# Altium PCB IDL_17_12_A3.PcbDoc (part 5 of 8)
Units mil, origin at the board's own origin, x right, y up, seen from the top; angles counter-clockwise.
Board outline 5119.97 x 10350 mil, 6 copper layers (Top Signal, 3.3 Volt, GND, 5 Volt, Split Plane, Bot Signal), stack 66.2 mil thick; 510 components, 178 nets, 2317 pads, 385 vias.
Unrouted connection lines stored in the file: 1.
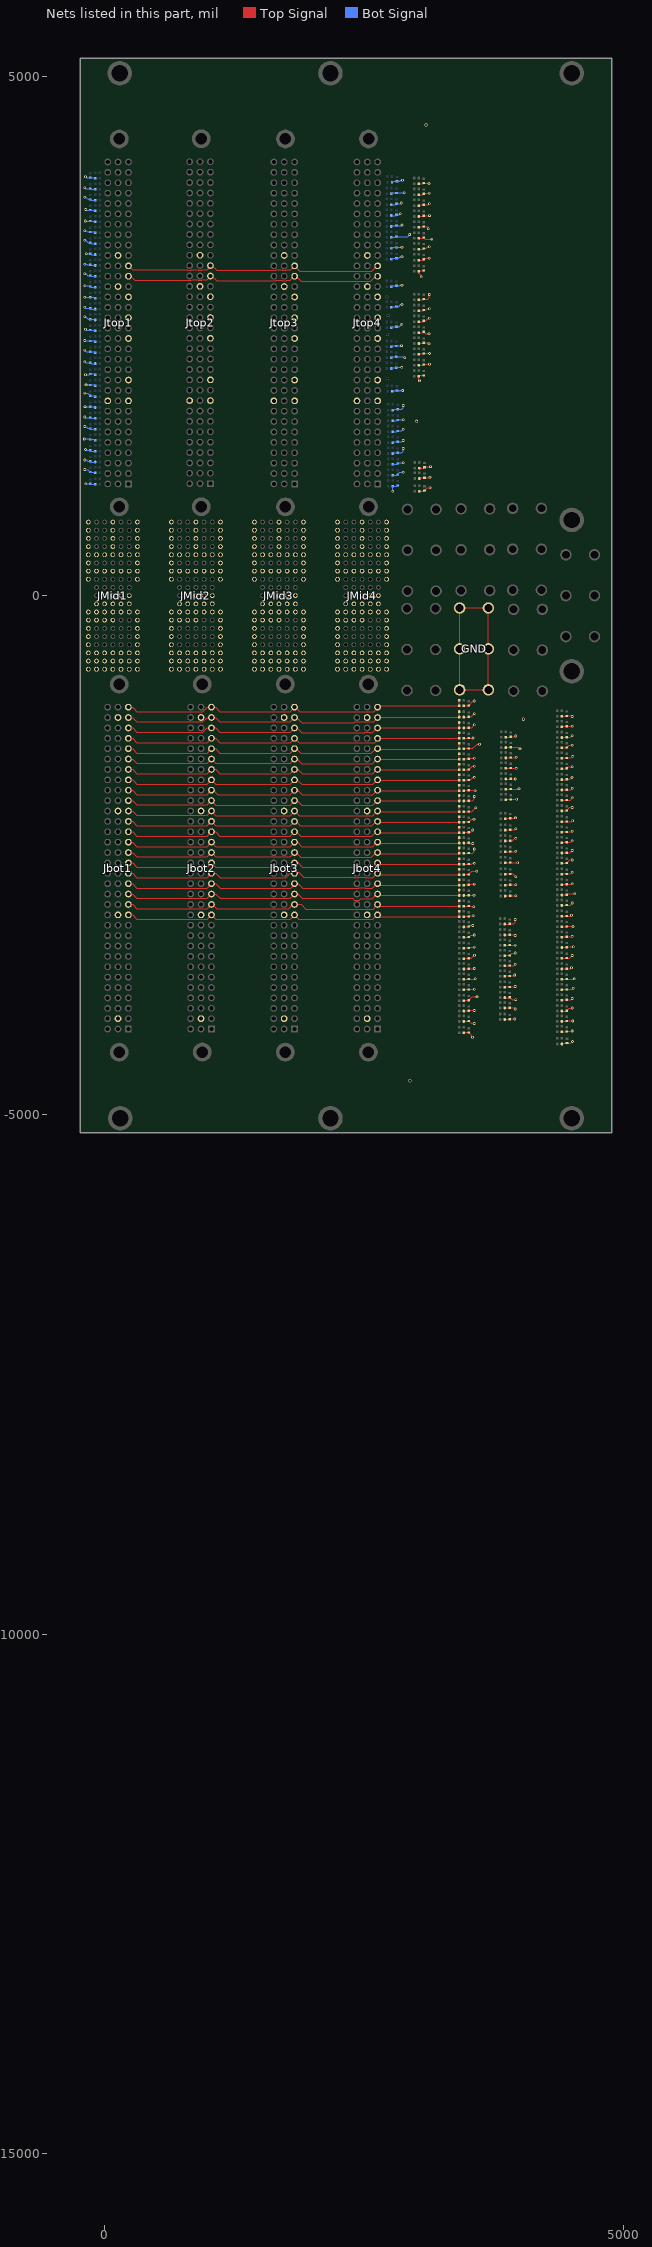
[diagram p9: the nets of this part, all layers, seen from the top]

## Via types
v1: diameter 25.59, hole 11.81, Top Signal to Bot Signal, 385 vias

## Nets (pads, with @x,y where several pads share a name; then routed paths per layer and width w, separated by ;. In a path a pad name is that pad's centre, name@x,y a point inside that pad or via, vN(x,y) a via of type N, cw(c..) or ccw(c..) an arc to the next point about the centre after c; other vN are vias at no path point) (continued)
GND: CR_IDL_17_12_TerA1.1 CR_IDL_17_12_TerA2.1 CR_IDL_17_12_TerA3.1 CR_IDL_17_12_TerA4.1 CR_IDL_17_12_TerA5.1 CR_IDL_17_12_TerA6.1 CR_IDL_17_12_TerA7.1 CR_IDL_17_12_TerA8.1 CR_IDL_17_12_TerA9.1 CR_IDL_17_12_TerA10.1 CR_IDL_17_12_TerA11.1 CR_IDL_17_12_TerA12.1 CR_IDL_17_12_TerA13.1 CR_IDL_17_12_TerA14.1 CR_IDL_17_12_TerA15.1 CR_IDL_17_12_TerA16.1 CR_IDL_17_12_TerA17.1 CR_IDL_17_12_TerA18.1 CR_IDL_17_12_TerA19.1 CR_IDL_17_12_TerA20.1 CR_IDL_17_12_TerA21.1 CR_IDL_17_12_TerA22.1 CR_IDL_17_12_TerA23.1 CR_IDL_17_12_TerA24.1 CR_IDL_17_12_TerA25.1 CR_IDL_17_12_TerA26.1 CR_IDL_17_12_TerA27.1 CR_IDL_17_12_TerA28.1 CR_IDL_17_12_TerA29.1 CR_IDL_17_12_TerA30.1 CR_IDL_17_12_TerA31.1 CR_IDL_17_12_TerA32.1 CR_IDL_17_12_TerA33.1 CR_IDL_17_12_TerA34.1 CR_IDL_17_12_TerA35.1 CR_IDL_17_12_TerA36.1 CR_IDL_17_12_TerA37.1 CR_IDL_17_12_TerA38.1 CR_IDL_17_12_TerA39.1 CR_IDL_17_12_TerA40.1 CR_IDL_17_12_TerA41.1 CR_IDL_17_12_TerA42.1 CR_IDL_17_12_TerA43.1 CR_IDL_17_12_TerA44.1 CR_IDL_17_12_TerA45.1 CR_IDL_17_12_TerA46.1 CR_IDL_17_12_TerA47.1 CR_IDL_17_12_TerA48.1 CR_IDL_17_12_TerA49.1 CR_IDL_17_12_TerA50.1 CR_IDL_17_12_TerA51.1 CR_IDL_17_12_TerA52.1 CR_IDL_17_12_TerA53.1 CR_IDL_17_12_TerA54.1 CR_IDL_17_12_TerA55.1 CR_IDL_17_12_TerA56.1 CR_IDL_17_12_TerA57.1 CR_IDL_17_12_TerA58.1 CR_IDL_17_12_TerA59.1 CR_IDL_17_12_TerA60.1 CR_IDL_17_12_TerA61.1 CR_IDL_17_12_TerA62.1 CR_IDL_17_12_TerA63.1 CR_IDL_17_12_TerA64.1 CR_IDL_17_12_TerA65.1 CR_IDL_17_12_TerA66.1 CR_IDL_17_12_TerA67.1 CR_IDL_17_12_TerA68.1 CR_IDL_17_12_TerA69.1 CR_IDL_17_12_TerA70.1 CR_IDL_17_12_TerA71.1 CR_IDL_17_12_TerA72.1 CRB_IDL_17_12_TerB1.1 CRB_IDL_17_12_TerB2.1 CRB_IDL_17_12_TerB3.1 CRB_IDL_17_12_TerB4.1 CRB_IDL_17_12_TerB5.1 CRB_IDL_17_12_TerB6.1 CRB_IDL_17_12_TerB7.1 CRB_IDL_17_12_TerB8.1 CRB_IDL_17_12_TerB9.1 CRB_IDL_17_12_TerB10.1 CRB_IDL_17_12_TerB11.1 CRB_IDL_17_12_TerB12.1 CRB_IDL_17_12_TerB13.1 CRB_IDL_17_12_TerB14.1 CRB_IDL_17_12_TerB15.1 CRB_IDL_17_12_TerB16.1 CRB_IDL_17_12_TerB17.1 CRB_IDL_17_12_TerB18.1 CRB_IDL_17_12_TerB19.1 CRB_IDL_17_12_TerB20.1 CRB_IDL_17_12_TerB21.1 CRB_IDL_17_12_TerB22.1 CRB_IDL_17_12_TerB23.1 CRB_IDL_17_12_TerB24.1 CRB_IDL_17_12_TerB25.1 CRB_IDL_17_12_TerB26.1 CRB_IDL_17_12_TerB27.1 CRB_IDL_17_12_TerB28.1 CRB_IDL_17_12_TerB29.1 CRB_IDL_17_12_TerB30.1 CRB_IDL_17_12_TerB31.1 CRB_IDL_17_12_TerB32.1 CRB_IDL_17_12_TerB33.1 CRB_IDL_17_12_TerB34.1 CRB_IDL_17_12_TerB35.1 CRB_IDL_17_12_TerB36.1 CRB_IDL_17_12_TerB37.1 CRB_IDL_17_12_TerB38.1 CRB_IDL_17_12_TerB39.1 CRB_IDL_17_12_TerB40.1 CRB_IDL_17_12_TerB41.1 CRB_IDL_17_12_TerB42.1 CRB_IDL_17_12_TerB43.1 CRB_IDL_17_12_TerB44.1 CRB_IDL_17_12_TerB45.1 CRB_IDL_17_12_TerB46.1 CRB_IDL_17_12_TerB47.1 CRB_IDL_17_12_TerB48.1 CRB_IDL_17_12_TerB49.1 CRB_IDL_17_12_TerB50.1 CRB_IDL_17_12_TerB51.1 CRB_IDL_17_12_TerB52.1 CRB_IDL_17_12_TerB53.1 CRB_IDL_17_12_TerB54.1 CRB_IDL_17_12_TerB55.1 CRB_IDL_17_12_TerB56.1 CRB_IDL_17_12_TerB57.1 CRB_IDL_17_12_TerB58.1 CRB_IDL_17_12_TerB59.1 CRB_IDL_17_12_TerB60.1 CRB_IDL_17_12_TerB61.1 CRB_IDL_17_12_TerB62.1 CRB_IDL_17_12_TerB63.1 CRB_IDL_17_12_TerB64.1 CRB_IDL_17_12_TerB65.1 CRB_IDL_17_12_TerB66.1 CRB_IDL_17_12_TerB67.1 CRB_IDL_17_12_TerB68.1 CRB_IDL_17_12_TerB69.1 CRB_IDL_17_12_TerB70.1 CRB_IDL_17_12_TerB71.1 CRB_IDL_17_12_TerB72.1 CRB_IDL_17_12_TerB73.1 CRB_IDL_17_12_TerB74.1 CRB_IDL_17_12_TerB75.1 CRB_IDL_17_12_TerB76.1 CRB_IDL_17_12_TerB77.1 CRB_IDL_17_12_TerB78.1 CRB_IDL_17_12_TerB79.1 CRB_IDL_17_12_TerB80.1 CRB_IDL_17_12_TerB81.1 CRB_IDL_17_12_TerB82.1 CRB_IDL_17_12_TerB83.1 CRB_IDL_17_12_TerB84.1 CRB_IDL_17_12_TerB85.1 CRB_IDL_17_12_TerB86.1 CRB_IDL_17_12_TerB87.1 CRB_IDL_17_12_TerB88.1 CRB_IDL_17_12_TerB89.1 GND.1 GND.2 GND.3 GND.4 GND.5 GND.6 Jbot1.B2 Jbot1.B12 Jbot1.B22 Jbot1.B31 Jbot2.B2 Jbot2.B12 Jbot2.B22 Jbot2.B31 Jbot3.B2 Jbot3.B12 Jbot3.B22 Jbot3.B31 Jbot4.B2 Jbot4.B12 Jbot4.B22 Jbot4.B31 JMid1.1 JMid1.2 JMid1.3 JMid1.4 JMid1.5 JMid1.6 JMid1.7 JMid1.8 JMid1.9 JMid1.10 JMid1.11 JMid1.12 JMid1.13 JMid1.14 JMid1.15 JMid1.16 JMid1.17 JMid1.18 JMid1.19 JMid1.24 JMid1.25 JMid1.26 JMid1.29 JMid1.31 JMid1.36 JMid1.37 JMid1.38 JMid1.43 JMid1.44 JMid1.45 JMid1.48 JMid1.50 JMid1.55 JMid1.56 JMid1.57 JMid1.61 JMid1.62 JMid1.63 JMid1.64 JMid1.67 JMid1.69 JMid1.70 JMid1.71 JMid1.72 JMid1.73 JMid1.74 JMid1.75 JMid1.76 JMid1.80 JMid1.81 JMid1.82 JMid1.86 JMid1.88 JMid1.93 JMid1.94 JMid1.95 JMid1.99 JMid1.100 JMid1.101 JMid1.105 JMid1.107 JMid1.112 JMid1.113 JMid1.114 JMid1.115 JMid1.116 JMid1.117 JMid1.118 JMid1.119 JMid1.120 JMid1.121 JMid1.122 JMid1.123 JMid1.124 JMid1.125 JMid1.126 JMid1.127 JMid2.1 JMid2.2 JMid2.3 JMid2.4 JMid2.5 JMid2.6 JMid2.7 JMid2.8 JMid2.9 JMid2.10 JMid2.11 JMid2.12 JMid2.13 JMid2.14 JMid2.15 JMid2.16 JMid2.17 JMid2.18 JMid2.19 JMid2.24 JMid2.25 JMid2.26 JMid2.29 JMid2.31 JMid2.36 JMid2.37 JMid2.38 JMid2.43 JMid2.44 JMid2.45 JMid2.48 JMid2.50 JMid2.55 JMid2.56 JMid2.57 JMid2.61 JMid2.62 JMid2.63 JMid2.64 JMid2.67 JMid2.69 JMid2.70 JMid2.71 JMid2.72 JMid2.73 JMid2.74 JMid2.75 JMid2.76 JMid2.80 JMid2.81 JMid2.82 JMid2.86 JMid2.88 JMid2.93 JMid2.94 JMid2.95 JMid2.99 JMid2.100 JMid2.101 JMid2.105 JMid2.107 JMid2.112 JMid2.113 JMid2.114 JMid2.115 JMid2.116 JMid2.117 JMid2.118 JMid2.119 JMid2.120 JMid2.121 JMid2.122 JMid2.123 JMid2.124 JMid2.125 JMid2.126 JMid2.127 JMid3.1 JMid3.2 JMid3.3 JMid3.4 JMid3.5 JMid3.6 JMid3.7 JMid3.8 JMid3.9 JMid3.10 JMid3.11 JMid3.12 JMid3.13 JMid3.14 JMid3.15 JMid3.16 JMid3.17 JMid3.18 JMid3.19 JMid3.24 JMid3.25 JMid3.26 JMid3.29 JMid3.31 JMid3.36 JMid3.37 JMid3.38 JMid3.43 JMid3.44 JMid3.45 JMid3.48 JMid3.50 JMid3.55 JMid3.56 JMid3.57 JMid3.61 JMid3.62 JMid3.63 JMid3.64 JMid3.67 JMid3.69 JMid3.70 JMid3.71 JMid3.72 JMid3.73 JMid3.74 JMid3.75 JMid3.76 JMid3.80 JMid3.81 JMid3.82 JMid3.86 JMid3.88 JMid3.93 JMid3.94 JMid3.95 JMid3.99 JMid3.100 JMid3.101 JMid3.105 JMid3.107 JMid3.112 JMid3.113 JMid3.114 JMid3.115 JMid3.116 JMid3.117 JMid3.118 JMid3.119 JMid3.120 JMid3.121 JMid3.122 JMid3.123 JMid3.124 JMid3.125 JMid3.126 JMid3.127 JMid4.1 JMid4.2 JMid4.3 JMid4.4 JMid4.5 JMid4.6 JMid4.7 JMid4.8 JMid4.9 JMid4.10 JMid4.11 JMid4.12 JMid4.13 JMid4.14 JMid4.15 JMid4.16 JMid4.17 JMid4.18 JMid4.19 JMid4.24 JMid4.25 JMid4.26 JMid4.29 JMid4.31 JMid4.36 JMid4.37 JMid4.38 JMid4.43 JMid4.44 JMid4.45 JMid4.48 JMid4.50 JMid4.55 JMid4.56 JMid4.57 JMid4.61 JMid4.62 JMid4.63 JMid4.64 JMid4.67 JMid4.69 JMid4.70 JMid4.71 JMid4.72 JMid4.73 JMid4.74 JMid4.75 JMid4.76 JMid4.80 JMid4.81 JMid4.82 JMid4.86 JMid4.88 JMid4.93 JMid4.94 JMid4.95 JMid4.99 JMid4.100 JMid4.101 JMid4.105 JMid4.107 JMid4.112 JMid4.113 JMid4.114 JMid4.115 JMid4.116 JMid4.117 JMid4.118 JMid4.119 JMid4.120 JMid4.121 JMid4.122 JMid4.123 JMid4.124 JMid4.125 JMid4.126 JMid4.127 Jtop1.A9 Jtop1.A11 Jtop1.A15 Jtop1.A17 Jtop1.A19 Jtop1.B20 Jtop1.B23 Jtop1.C9 Jtop2.A9 Jtop2.A11 Jtop2.A15 Jtop2.A17 Jtop2.A19 Jtop2.B20 Jtop2.B23 Jtop2.C9 Jtop3.A9 Jtop3.A11 Jtop3.A15 Jtop3.A17 Jtop3.A19 Jtop3.B20 Jtop3.B23 Jtop3.C9 Jtop4.A9 Jtop4.A11 Jtop4.A15 Jtop4.A17 Jtop4.A19 Jtop4.B20 Jtop4.B23 Jtop4.C9 R2R_IDL_17_12_TerA1.1 R2R_IDL_17_12_TerA2.1 R2R_IDL_17_12_TerA3.1 R2R_IDL_17_12_TerA4.1 R2R_IDL_17_12_TerA5.1 R2R_IDL_17_12_TerA6.1 R2R_IDL_17_12_TerA7.1 R2R_IDL_17_12_TerA8.1 R2R_IDL_17_12_TerA9.1 R2R_IDL_17_12_TerA10.1 R2R_IDL_17_12_TerA11.1 R2R_IDL_17_12_TerA12.1 R2R_IDL_17_12_TerA13.1 R2R_IDL_17_12_TerA14.1 R2R_IDL_17_12_TerA15.1 R2R_IDL_17_12_TerA16.1 R2R_IDL_17_12_TerA17.1 R2R_IDL_17_12_TerA18.1 R2R_IDL_17_12_TerA19.1 R2R_IDL_17_12_TerA20.1 R2R_IDL_17_12_TerA21.1 R2R_IDL_17_12_TerA22.1 R2R_IDL_17_12_TerA23.1 R2R_IDL_17_12_TerA24.1 R2R_IDL_17_12_TerA25.1 R2R_IDL_17_12_TerA26.1 R2R_IDL_17_12_TerA27.1 R2R_IDL_17_12_TerA28.1 R2R_IDL_17_12_TerA29.1 R2R_IDL_17_12_TerA30.1 R2R_IDL_17_12_TerA31.1 R2R_IDL_17_12_TerA32.1 R2R_IDL_17_12_TerA33.1 R2R_IDL_17_12_TerA34.1 R2R_IDL_17_12_TerA35.1 R2R_IDL_17_12_TerA36.1 R2R_IDL_17_12_TerA37.1 R2R_IDL_17_12_TerA38.1 R2R_IDL_17_12_TerA39.1 R2R_IDL_17_12_TerA40.1 R2R_IDL_17_12_TerA41.1 R2R_IDL_17_12_TerA42.1 R2R_IDL_17_12_TerA43.1 R2R_IDL_17_12_TerA44.1 R2R_IDL_17_12_TerA45.1 R2R_IDL_17_12_TerA46.1 R2R_IDL_17_12_TerA47.1 R2R_IDL_17_12_TerA48.1 R2R_IDL_17_12_TerA49.1 R2R_IDL_17_12_TerA50.1 R2R_IDL_17_12_TerA51.1 R2R_IDL_17_12_TerA52.1 R2R_IDL_17_12_TerA53.1 R2R_IDL_17_12_TerA54.1 R2R_IDL_17_12_TerA55.1 R2R_IDL_17_12_TerA56.1 R2R_IDL_17_12_TerA57.1 R2R_IDL_17_12_TerA58.1 R2R_IDL_17_12_TerA59.1 R2R_IDL_17_12_TerA60.1 R2R_IDL_17_12_TerA61.1 R2R_IDL_17_12_TerA62.1 R2R_IDL_17_12_TerA63.1 R2R_IDL_17_12_TerA64.1 R2R_IDL_17_12_TerA65.1 R2R_IDL_17_12_TerA66.1 R2R_IDL_17_12_TerA67.1 R2R_IDL_17_12_TerA68.1 R2R_IDL_17_12_TerA69.1 R2R_IDL_17_12_TerA70.1 R2R_IDL_17_12_TerA71.1 R2R_IDL_17_12_TerA72.1 R2RB_IDL_17_12_TerB1.1 R2RB_IDL_17_12_TerB2.1 R2RB_IDL_17_12_TerB3.1 R2RB_IDL_17_12_TerB4.1 R2RB_IDL_17_12_TerB5.1 R2RB_IDL_17_12_TerB6.1 R2RB_IDL_17_12_TerB7.1 R2RB_IDL_17_12_TerB8.1 R2RB_IDL_17_12_TerB9.1 R2RB_IDL_17_12_TerB10.1 R2RB_IDL_17_12_TerB11.1 R2RB_IDL_17_12_TerB12.1 R2RB_IDL_17_12_TerB13.1 R2RB_IDL_17_12_TerB14.1 R2RB_IDL_17_12_TerB15.1 R2RB_IDL_17_12_TerB16.1 R2RB_IDL_17_12_TerB17.1 R2RB_IDL_17_12_TerB18.1 R2RB_IDL_17_12_TerB19.1 R2RB_IDL_17_12_TerB20.1 R2RB_IDL_17_12_TerB21.1 R2RB_IDL_17_12_TerB22.1 R2RB_IDL_17_12_TerB23.1 R2RB_IDL_17_12_TerB24.1 R2RB_IDL_17_12_TerB25.1 R2RB_IDL_17_12_TerB26.1 R2RB_IDL_17_12_TerB27.1 R2RB_IDL_17_12_TerB28.1 R2RB_IDL_17_12_TerB29.1 R2RB_IDL_17_12_TerB30.1 R2RB_IDL_17_12_TerB31.1 R2RB_IDL_17_12_TerB32.1 R2RB_IDL_17_12_TerB33.1 R2RB_IDL_17_12_TerB34.1 R2RB_IDL_17_12_TerB35.1 R2RB_IDL_17_12_TerB36.1 R2RB_IDL_17_12_TerB37.1 R2RB_IDL_17_12_TerB38.1 R2RB_IDL_17_12_TerB39.1 R2RB_IDL_17_12_TerB40.1 R2RB_IDL_17_12_TerB41.1 R2RB_IDL_17_12_TerB42.1 R2RB_IDL_17_12_TerB43.1 R2RB_IDL_17_12_TerB44.1 R2RB_IDL_17_12_TerB45.1 R2RB_IDL_17_12_TerB46.1 R2RB_IDL_17_12_TerB47.1 R2RB_IDL_17_12_TerB48.1 R2RB_IDL_17_12_TerB49.1 R2RB_IDL_17_12_TerB50.1 R2RB_IDL_17_12_TerB51.1 R2RB_IDL_17_12_TerB52.1 R2RB_IDL_17_12_TerB53.1 R2RB_IDL_17_12_TerB54.1 R2RB_IDL_17_12_TerB55.1 R2RB_IDL_17_12_TerB56.1 R2RB_IDL_17_12_TerB57.1 R2RB_IDL_17_12_TerB58.1 R2RB_IDL_17_12_TerB59.1 R2RB_IDL_17_12_TerB60.1 R2RB_IDL_17_12_TerB61.1 R2RB_IDL_17_12_TerB62.1 R2RB_IDL_17_12_TerB63.1 R2RB_IDL_17_12_TerB64.1 R2RB_IDL_17_12_TerB65.1 R2RB_IDL_17_12_TerB66.1 R2RB_IDL_17_12_TerB67.1 R2RB_IDL_17_12_TerB68.1 R2RB_IDL_17_12_TerB69.1 R2RB_IDL_17_12_TerB70.1 R2RB_IDL_17_12_TerB71.1 R2RB_IDL_17_12_TerB72.1 R2RB_IDL_17_12_TerB73.1 R2RB_IDL_17_12_TerB74.1 R2RB_IDL_17_12_TerB75.1 R2RB_IDL_17_12_TerB76.1 R2RB_IDL_17_12_TerB77.1 R2RB_IDL_17_12_TerB78.1 R2RB_IDL_17_12_TerB79.1 R2RB_IDL_17_12_TerB80.1 R2RB_IDL_17_12_TerB81.1 R2RB_IDL_17_12_TerB82.1 R2RB_IDL_17_12_TerB83.1 R2RB_IDL_17_12_TerB84.1 R2RB_IDL_17_12_TerB85.1 R2RB_IDL_17_12_TerB86.1 R2RB_IDL_17_12_TerB87.1 R2RB_IDL_17_12_TerB88.1 R2RB_IDL_17_12_TerB89.1 | length 17891.3
  Top Signal w8: Jtop1.A11@228.79,2082.06 Jtop1.A11@229.21,2082.48 ; Jtop3.C9@1628.3,1882.48 Jtop3.C9@1628.72,1882.06 ; Jtop3.A19@1817.47,2880.07 Jtop3.A19@1826.73,2880.07 ; Jtop3.A19@1828.72,2882.06 Jtop3.A19@1826.73,2880.07 ; Jtop3.A19@1857.75,2880.07 Jtop3.A19@1826.73,2880.07 ; R2R_IDL_17_12_TerA39.1@3025.29,2218.34 3065.6,2218.34 CR_IDL_17_12_TerA39.1@3073.37,2226.12 3074.67,2227.41 v1(3128.29,2227.41) ; R2R_IDL_17_12_TerA38.1@3025.29,2323.34 3033.06,2331.12 CR_IDL_17_12_TerA38.1@3073.37,2331.12 3074.52,2332.27 v1(3127.41,2332.27) ; R2R_IDL_17_12_TerA37.1@3025.29,2428.34 3065.6,2428.34 CR_IDL_17_12_TerA37.1@3073.37,2436.12 3112.93,2436.12 v1(3123.96,2425.09) ; R2R_IDL_17_12_TerA36.1@3025.29,2533.34 3065.6,2533.34 CR_IDL_17_12_TerA36.1@3073.37,2541.12 3091.94,2522.55 v1(3122.86,2522.55) ; R2R_IDL_17_12_TerA35.1@3025.29,2638.34 3065.6,2638.34 CR_IDL_17_12_TerA35.1@3073.37,2646.12 3092.05,2646.12 3116.7,2670.77 v1(3126.89,2670.77) ; R2R_IDL_17_12_TerA34.1@3025.29,2743.34 3065.6,2743.34 CR_IDL_17_12_TerA34.1@3073.37,2751.12 3098.55,2751.12 3110.2,2762.77 v1(3126.89,2762.77) ; R2R_IDL_17_12_TerA33.1@3025.29,2848.34 3065.6,2848.34 CR_IDL_17_12_TerA33.1@3073.37,2856.12 3110.77,2856.12 3126.89,2872.24 v1(3126.89,2900.77) ; R2R_IDL_17_12_TerA31.1@3025.29,3231.34 3065.6,3231.34 CR_IDL_17_12_TerA31.1@3073.37,3239.12 3084.04,3249.78 v1(3126.36,3249.78) ; R2R_IDL_17_12_TerA30.1@3025.29,3336.34 3065.6,3336.34 CR_IDL_17_12_TerA30.1@3073.37,3344.12 3096.05,3344.12 3112.7,3360.77 v1(3126.89,3360.77) ; R2R_IDL_17_12_TerA29.1@3025.29,3441.34 3065.6,3441.34 CR_IDL_17_12_TerA29.1@3073.37,3449.12 3088.91,3433.58 3150.71,3433.58 v1(3150.9,3433.4) ; R2R_IDL_17_12_TerA28.1@3025.29,3546.34 3033.06,3554.12 CR_IDL_17_12_TerA28.1@3073.37,3554.12 3110.77,3554.12 3116.74,3548.15 v1(3116.74,3534.29) ; R2R_IDL_17_12_TerA27.1@3025.29,3651.34 3065.6,3651.34 CR_IDL_17_12_TerA27.1@3073.37,3659.12 3074.33,3660.07 v1(3128.73,3660.07) ; R2R_IDL_17_12_TerA26.1@3025.29,3756.34 3033.06,3764.12 CR_IDL_17_12_TerA26.1@3073.37,3764.12 3116.24,3764.12 v1(3126.89,3774.77) ; R2R_IDL_17_12_TerA25.1@3025.29,3861.34 3064.57,3861.34 3072.34,3869.12 CR_IDL_17_12_TerA25.1@3073.37,3869.12 3080.95,3876.7 v1(3126.02,3876.7) ; R2R_IDL_17_12_TerA24.1@3025.29,3966.34 3065.6,3966.34 CR_IDL_17_12_TerA24.1@3073.37,3974.12 3077.96,3969.53 v1(3122.77,3969.53) ; R2R_IDL_17_12_TerA43.1@3031.12,1004.85 3071.43,1004.85 CR_IDL_17_12_TerA43.1@3079.2,1012.62 3106.64,1040.06 v1(3133.78,1040.06) ; R2R_IDL_17_12_TerA41.1@3031.19,1227.82 3071.5,1227.82 CR_IDL_17_12_TerA41.1@3079.27,1235.59 3086.41,1242.73 v1(3137.97,1242.73) ; v1(3031.67,2067.98) 3025.29,2074.36 R2R_IDL_17_12_TerA40.1@3025.29,2113.34 3033.06,2121.12 CR_IDL_17_12_TerA40.1@3073.37,2121.12 ; R2R_IDL_17_12_TerA42.1@3034.79,1135.59 CR_IDL_17_12_TerA42.1@3079.27,1135.59 3127.14,1135.59 v1(3132.79,1141.25) ; v1(3049.64,3069.82) 3049.64,3080.17 3025.29,3104.51 R2R_IDL_17_12_TerA32.1@3025.29,3123.34 3033.06,3131.12 CR_IDL_17_12_TerA32.1@3073.37,3131.12 ; R2RB_IDL_17_12_TerB1.1@3457.61,-1061.69 3502.89,-1061.69 CRB_IDL_17_12_TerB1.1@3505.91,-1058.68 3550.59,-1014 v1(3559.43,-1014) ; R2RB_IDL_17_12_TerB30.1@3458.3,-4000.17 3461.31,-3997.15 CRB_IDL_17_12_TerB30.1@3506.6,-3997.15 3509.55,-3994.21 v1(3559.31,-3994.21) ; R2RB_IDL_17_12_TerB29.1@3458.3,-3900.17 3461.31,-3897.15 CRB_IDL_17_12_TerB29.1@3506.6,-3897.15 3540.08,-3863.68 v1(3585.44,-3863.68) ; R2RB_IDL_17_12_TerB28.1@3458.3,-3795.17 3461.31,-3792.15 CRB_IDL_17_12_TerB28.1@3506.6,-3792.15 3557.97,-3792.15 v1(3560.12,-3790) ; R2RB_IDL_17_12_TerB27.1@3458.3,-3695.17 3461.31,-3692.15 CRB_IDL_17_12_TerB27.1@3506.6,-3692.15 3566.01,-3692.15 v1(3569.31,-3688.85) ; R2RB_IDL_17_12_TerB26.1@3458.3,-3595.17 3461.31,-3592.15 CRB_IDL_17_12_TerB26.1@3506.6,-3592.15 3557.97,-3592.15 v1(3560.12,-3590) ; R2RB_IDL_17_12_TerB25.1@3458.3,-3495.17 3461.31,-3492.15 CRB_IDL_17_12_TerB25.1@3506.6,-3492.15 3531.92,-3492.15 v1(3560.76,-3463.32) ; R2RB_IDL_17_12_TerB24.1@3458.3,-3395.17 3461.31,-3392.15 CRB_IDL_17_12_TerB24.1@3506.6,-3392.15 3514.35,-3384.4 v1(3559.62,-3384.4) ; R2RB_IDL_17_12_TerB23.1@3458.3,-3290.17 3461.31,-3287.15 CRB_IDL_17_12_TerB23.1@3506.6,-3287.15 3525.75,-3268 v1(3560.12,-3268) ; R2RB_IDL_17_12_TerB22.1@3458.3,-3190.17 3461.31,-3187.15 CRB_IDL_17_12_TerB22.1@3506.6,-3187.15 3521.67,-3172.08 3540.2,-3172.08 v1(3544.12,-3176) ; R2RB_IDL_17_12_TerB21.1@3458.3,-3092.17 3461.31,-3089.15 CRB_IDL_17_12_TerB21.1@3506.6,-3089.15 3512.92,-3082.83 v1(3548.27,-3082.83) ; R2RB_IDL_17_12_TerB20.1@3458.3,-2992.17 3503.59,-2992.17 CRB_IDL_17_12_TerB20.1@3506.6,-2989.15 3546.79,-2989.15 v1(3553.18,-2995.54) ; R2RB_IDL_17_12_TerB19.1@3458.3,-2887.17 3551.61,-2887.17 3554.63,-2884.15 v1(3556.39,-2885.92) ; R2RB_IDL_17_12_TerB18.1@3458.3,-2787.17 3461.31,-2784.15 CRB_IDL_17_12_TerB18.1@3506.6,-2784.15 3512.75,-2778 v1(3560.12,-2778) ; R2RB_IDL_17_12_TerB17.1@3458.3,-2687.17 3461.31,-2684.15 CRB_IDL_17_12_TerB17.1@3506.6,-2684.15 3535.8,-2654.95 v1(3583.75,-2654.95) ; R2RB_IDL_17_12_TerB16.1@3458.3,-2587.17 3461.31,-2584.15 CRB_IDL_17_12_TerB16.1@3506.6,-2584.15 3534.53,-2584.15 3540.68,-2578 v1(3560.12,-2578) ; R2RB_IDL_17_12_TerB15.1@3458.3,-2482.17 3481,-2482.17 3484.02,-2479.15 CRB_IDL_17_12_TerB15.1@3506.6,-2479.15 3544,-2479.15 3560.12,-2463.03 v1(3560.12,-2440) ; R2RB_IDL_17_12_TerB14.1@3458.3,-2382.17 3461.31,-2379.15 CRB_IDL_17_12_TerB14.1@3506.6,-2379.15 3514.16,-2386.71 v1(3545.43,-2386.71) ; R2RB_IDL_17_12_TerB13.1@3458.3,-2282.17 3461.31,-2279.15 CRB_IDL_17_12_TerB13.1@3506.6,-2279.15 3525.4,-2279.15 3544.12,-2260.43 v1(3544.12,-2256) ; R2RB_IDL_17_12_TerB12.1@3458.3,-2182.17 3461.31,-2179.15 CRB_IDL_17_12_TerB12.1@3506.6,-2179.15 3533.23,-2152.53 v1(3555.98,-2152.53) ; R2RB_IDL_17_12_TerB11.1@3458.3,-2082.17 3461.31,-2079.15 CRB_IDL_17_12_TerB11.1@3506.6,-2079.15 3536.97,-2079.15 v1(3572.88,-2043.24) ; R2RB_IDL_17_12_TerB10.1@3458.3,-1977.17 3461.31,-1974.15 CRB_IDL_17_12_TerB10.1@3506.6,-1974.15 3544,-1974.15 3560.12,-1958.03 v1(3560.12,-1934) ; R2RB_IDL_17_12_TerB9.1@3458.3,-1877.17 3461.31,-1874.15 CRB_IDL_17_12_TerB9.1@3506.6,-1874.15 3562.02,-1874.15 v1(3567.05,-1879.19) ; R2RB_IDL_17_12_TerB8.1@3458.3,-1777.17 3481,-1777.17 3484.02,-1774.15 CRB_IDL_17_12_TerB8.1@3506.6,-1774.15 3525.53,-1774.15 3549.68,-1750 v1(3560.12,-1750) ; R2RB_IDL_17_12_TerB7.1@3458.3,-1677.17 3461.31,-1674.15 CRB_IDL_17_12_TerB7.1@3506.6,-1674.15 3538.75,-1642 v1(3560.12,-1642) ; R2RB_IDL_17_12_TerB6.1@3458.3,-1574.17 3461.31,-1571.15 CRB_IDL_17_12_TerB6.1@3506.6,-1571.15 3511.75,-1566 v1(3560.12,-1566) ; R2RB_IDL_17_12_TerB5.1@3458.3,-1474.17 3461.31,-1471.15 CRB_IDL_17_12_TerB5.1@3506.6,-1471.15 3546.94,-1471.15 3587.39,-1430.7 v1(3608.85,-1430.7) ; R2RB_IDL_17_12_TerB4.1@3458.3,-1374.17 3461.31,-1371.15 CRB_IDL_17_12_TerB4.1@3506.6,-1371.15 v1(3546.62,-1371.15) ; R2RB_IDL_17_12_TerB3.1@3458.3,-1274.17 3461.31,-1271.15 CRB_IDL_17_12_TerB3.1@3506.6,-1271.15 3532.97,-1271.15 v1(3560.12,-1244) ; R2RB_IDL_17_12_TerB2.1@3458.3,-1169.17 3503.59,-1169.17 CRB_IDL_17_12_TerB2.1@3506.6,-1166.15 3529.97,-1166.15 v1(3560.12,-1136) ; R2RB_IDL_17_12_TerB31.1@3463.14,-4097.15 CRB_IDL_17_12_TerB31.1@3506.6,-4097.15 3529.08,-4119.63 v1(3558.85,-4119.63) ; R2RB_IDL_17_12_TerB32.1@3465.91,-4206.21 CRB_IDL_17_12_TerB32.1@3506.2,-4206.21 3541.7,-4241.71 v1(3541.7,-4252.42) ; R2RB_IDL_17_12_TerB57.1@3849,-4081.98 3852.62,-4078.36 CRB_IDL_17_12_TerB57.1@3900.51,-4078.36 3902.59,-4076.28 v1(3949.29,-4076.28) ; R2RB_IDL_17_12_TerB47.1@3851.47,-2889.39 CRB_IDL_17_12_TerB47.1@3905.55,-2889.39 v1@3959.07,-2889.39 ; R2RB_IDL_17_12_TerB55.1@3852.25,-3870.4 3897.54,-3870.4 CRB_IDL_17_12_TerB55.1@3900.55,-3867.39 3923.27,-3890.1 v1(3959.21,-3890.1) ; R2RB_IDL_17_12_TerB53.1@3852.25,-3665.4 3855.26,-3662.39 CRB_IDL_17_12_TerB53.1@3900.55,-3662.39 3937.95,-3662.39 v1(3947.65,-3652.6) v1(3947.65,-3652.6) ; R2RB_IDL_17_12_TerB52.1@3852.25,-3565.4 3855.26,-3562.39 CRB_IDL_17_12_TerB52.1@3900.55,-3562.39 3940.92,-3562.39 v1(3954.07,-3549.23) ; R2RB_IDL_17_12_TerB51.1@3852.25,-3467.4 3855.26,-3464.39 CRB_IDL_17_12_TerB51.1@3900.55,-3464.39 3923.7,-3441.23 v1(3954.07,-3441.23) ; R2RB_IDL_17_12_TerB50.1@3852.25,-3367.4 3855.26,-3364.39 CRB_IDL_17_12_TerB50.1@3900.55,-3364.39 3953.22,-3364.39 v1(3954.07,-3365.23) ; R2RB_IDL_17_12_TerB48.1@3852.25,-3162.4 3897.54,-3162.4 CRB_IDL_17_12_TerB48.1@3900.55,-3159.39 3937.95,-3159.39 3954.07,-3143.27 v1(3954.07,-3119.23) ; R2RB_IDL_17_12_TerB56.1@3854.52,-3967.39 CRB_IDL_17_12_TerB56.1@3900.55,-3967.39 3941.41,-3967.39 v1(3954.7,-3980.68) ; R2RB_IDL_17_12_TerB41.1@3855.13,-2254.39 CRB_IDL_17_12_TerB41.1@3905.55,-2254.39 3949.92,-2254.39 v1(3959.07,-2245.23) ; R2RB_IDL_17_12_TerB54.1@3855.52,-3767.39 CRB_IDL_17_12_TerB54.1@3900.55,-3767.39 3949.92,-3767.39 v1(3954.07,-3763.23) ; R2RB_IDL_17_12_TerB49.1@3857.2,-3264.39 CRB_IDL_17_12_TerB49.1@3900.55,-3264.39 3945.22,-3264.39 v1(3954.07,-3273.23) ; R2RB_IDL_17_12_TerB43.1@3857.25,-2467.4 3879.95,-2467.4 3882.97,-2464.39 CRB_IDL_17_12_TerB43.1@3905.55,-2464.39 3955.92,-2464.39 v1(3959.07,-2461.23) ; R2RB_IDL_17_12_TerB42.1@3857.25,-2362.4 3902.54,-2362.4 CRB_IDL_17_12_TerB42.1@3905.55,-2359.39 3925.48,-2359.39 3947.63,-2337.23 v1(3959.07,-2337.23) ; R2RB_IDL_17_12_TerB40.1@3857.25,-2147.4 3860.26,-2144.39 CRB_IDL_17_12_TerB40.1@3905.55,-2144.39 3951.51,-2144.39 v1(3955.76,-2140.13) ; R2RB_IDL_17_12_TerB46.1@3857.78,-2784.39 CRB_IDL_17_12_TerB46.1@3905.55,-2784.39 3957.92,-2784.39 v1(3959.07,-2783.23) ; R2RB_IDL_17_12_TerB44.1@3858.34,-2571.76 v1(3976.53,-2571.76) ; R2RB_IDL_17_12_TerB45.1@3858.62,-2679.39 CRB_IDL_17_12_TerB45.1@3905.55,-2679.39 3931.22,-2679.39 v1(3959.07,-2707.23) ; R2RB_IDL_17_12_TerB38.1@3862.25,-1865.75 3865.26,-1862.73 CRB_IDL_17_12_TerB38.1@3910.55,-1862.73 3985.91,-1862.73 v1(3990.07,-1858.57) ; R2RB_IDL_17_12_TerB36.1@3862.25,-1662.75 3865.26,-1659.73 CRB_IDL_17_12_TerB36.1@3910.55,-1659.73 3960.57,-1659.73 v1(3964.07,-1663.23) ; R2RB_IDL_17_12_TerB35.1@3862.25,-1562.75 3865.26,-1559.73 CRB_IDL_17_12_TerB35.1@3910.55,-1559.73 3959.57,-1559.73 v1(3964.07,-1555.23) ; R2RB_IDL_17_12_TerB34.1@3862.25,-1462.75 3865.26,-1459.73 CRB_IDL_17_12_TerB34.1@3910.55,-1459.73 3979.92,-1459.73 ; R2RB_IDL_17_12_TerB33.1@3862.25,-1362.75 3907.54,-1362.75 CRB_IDL_17_12_TerB33.1@3910.55,-1359.73 3947.95,-1359.73 3958.34,-1349.34 v1(3958.34,-1351.37) ; R2RB_IDL_17_12_TerB37.1@3865.26,-1762.73 R2RB_IDL_17_12_TerB37.1@3862.25,-1765.75 3907.54,-1765.75 CRB_IDL_17_12_TerB37.1@3910.55,-1762.73 3956.57,-1762.73 3955.31,-1763.99 v1(3955.31,-1765.31) ; R2RB_IDL_17_12_TerB39.1@3866.86,-1962.73 CRB_IDL_17_12_TerB39.1@3910.55,-1962.73 3911.66,-1961.63 v1(3967.03,-1961.63) ; CRB_IDL_17_12_TerB44.1@3905.55,-2569.39 CRB_IDL_17_12_TerB44.1@3907.7,-2567.23 ; 3980.17,-1459.71 3995.86,-1475.4 v1(3999.54,-1475.4) ; R2RB_IDL_17_12_TerB88.1@4401.98,-4200.11 4447.27,-4200.11 CRB_IDL_17_12_TerB88.1@4450.29,-4197.09 4487.69,-4197.09 4501.53,-4183.25 v1(4501.53,-4191.94) ; R2RB_IDL_17_12_TerB87.1@4401.98,-4100.11 4405,-4097.09 CRB_IDL_17_12_TerB87.1@4450.29,-4097.09 4452.08,-4095.3 v1(4506.46,-4095.3) ; R2RB_IDL_17_12_TerB86.1@4401.98,-4000.11 4447.27,-4000.11 CRB_IDL_17_12_TerB86.1@4450.29,-3997.09 4475.92,-3971.46 v1(4503.81,-3971.46) ; R2RB_IDL_17_12_TerB85.1@4401.98,-3895.11 4405,-3892.09 CRB_IDL_17_12_TerB85.1@4450.29,-3892.09 4491.17,-3892.09 v1(4503.81,-3879.46) ; R2RB_IDL_17_12_TerB84.1@4401.98,-3795.11 4405,-3792.09 CRB_IDL_17_12_TerB84.1@4450.29,-3792.09 4502.4,-3792.09 v1(4513.2,-3781.29) ; R2RB_IDL_17_12_TerB83.1@4401.98,-3695.11 4447.27,-3695.11 CRB_IDL_17_12_TerB83.1@4450.29,-3692.09 4521.75,-3692.09 v1(4523.3,-3690.54) ; R2RB_IDL_17_12_TerB82.1@4401.98,-3595.11 4405,-3592.09 CRB_IDL_17_12_TerB82.1@4450.29,-3592.09 4487.69,-3592.09 v1(4495.75,-3584.03) ; R2RB_IDL_17_12_TerB81.1@4401.98,-3493.11 4405,-3490.09 CRB_IDL_17_12_TerB81.1@4450.29,-3490.09 4479.17,-3490.09 v1(4503.81,-3465.46) ; R2RB_IDL_17_12_TerB80.1@4401.98,-3388.11 4405,-3385.09 CRB_IDL_17_12_TerB80.1@4450.29,-3385.09 4455.39,-3379.98 v1(4513.61,-3379.98) ; R2RB_IDL_17_12_TerB79.1@4401.98,-3288.11 4405,-3285.09 CRB_IDL_17_12_TerB79.1@4450.29,-3285.09 4500.17,-3285.09 v1(4503.81,-3281.46) ; R2RB_IDL_17_12_TerB78.1@4401.98,-3188.11 4447.27,-3188.11 CRB_IDL_17_12_TerB78.1@4450.29,-3185.09 4508.68,-3185.09 v1(4509.36,-3185.77) ; R2RB_IDL_17_12_TerB77.1@4401.98,-3088.11 4405,-3085.09 CRB_IDL_17_12_TerB77.1@4450.29,-3085.09 4487.69,-3085.09 v1(4495.75,-3077.03) ; R2RB_IDL_17_12_TerB76.1@4401.98,-2983.11 4405,-2980.09 CRB_IDL_17_12_TerB76.1@4450.29,-2980.09 4483.17,-2980.09 v1(4503.81,-2959.46) ; R2RB_IDL_17_12_TerB75.1@4401.98,-2883.11 4405,-2880.09 CRB_IDL_17_12_TerB75.1@4450.29,-2880.09 4458.66,-2871.72 v1(4526.24,-2871.72) ; R2RB_IDL_17_12_TerB74.1@4401.98,-2783.11 4405,-2780.09 CRB_IDL_17_12_TerB74.1@4450.29,-2780.09 4499.17,-2780.09 v1(4503.81,-2775.46) ; R2RB_IDL_17_12_TerB73.1@4401.98,-2683.11 4405,-2680.09 CRB_IDL_17_12_TerB73.1@4450.29,-2680.09 4487.69,-2680.09 v1(4503.81,-2663.97) ; R2RB_IDL_17_12_TerB72.1@4401.98,-2578.11 4405,-2575.09 CRB_IDL_17_12_TerB72.1@4450.29,-2575.09 4479.92,-2545.46 v1(4503.81,-2545.46) ; R2RB_IDL_17_12_TerB71.1@4401.98,-2478.11 4405,-2475.09 CRB_IDL_17_12_TerB71.1@4450.29,-2475.09 4482.17,-2475.09 v1(4503.81,-2453.46) ; R2RB_IDL_17_12_TerB70.1@4401.98,-2378.11 4405,-2375.09 CRB_IDL_17_12_TerB70.1@4450.29,-2375.09 4490.17,-2375.09 v1(4503.81,-2361.46) ; R2RB_IDL_17_12_TerB69.1@4401.98,-2278.11 4405,-2275.09 CRB_IDL_17_12_TerB69.1@4450.29,-2275.09 4498.17,-2275.09 v1(4503.81,-2269.46) ; R2RB_IDL_17_12_TerB68.1@4401.98,-2178.11 4405,-2175.09 CRB_IDL_17_12_TerB68.1@4450.29,-2175.09 4497.94,-2175.09 v1(4506.16,-2166.87) ; R2RB_IDL_17_12_TerB67.1@4401.98,-2073.11 4447.27,-2073.11 CRB_IDL_17_12_TerB67.1@4450.29,-2070.09 4480.92,-2039.46 v1(4503.81,-2039.46) ; R2RB_IDL_17_12_TerB66.1@4401.98,-1971.11 4405,-1968.09 CRB_IDL_17_12_TerB66.1@4450.29,-1968.09 4483.17,-1968.09 v1(4503.81,-1947.46) ; R2RB_IDL_17_12_TerB65.1@4401.98,-1871.11 4405,-1868.09 CRB_IDL_17_12_TerB65.1@4450.29,-1868.09 4491.17,-1868.09 v1(4503.81,-1855.46) ; R2RB_IDL_17_12_TerB64.1@4401.98,-1771.11 4447.27,-1771.11 CRB_IDL_17_12_TerB64.1@4450.29,-1768.09 4478.97,-1768.09 4495.84,-1751.22 v1(4500.23,-1751.22) ; R2RB_IDL_17_12_TerB63.1@4401.98,-1666.11 4447.27,-1666.11 CRB_IDL_17_12_TerB63.1@4450.29,-1663.09 4466.4,-1646.97 v1(4503.81,-1646.97) ; R2RB_IDL_17_12_TerB62.1@4401.98,-1566.11 4405,-1563.09 CRB_IDL_17_12_TerB62.1@4450.29,-1563.09 4492.79,-1563.09 v1(4508.25,-1547.63) ; R2RB_IDL_17_12_TerB61.1@4401.98,-1466.11 4447.27,-1466.11 CRB_IDL_17_12_TerB61.1@4450.29,-1463.09 4471.92,-1441.46 v1(4503.81,-1441.46) ; R2RB_IDL_17_12_TerB60.1@4401.98,-1366.11 4405,-1363.09 CRB_IDL_17_12_TerB60.1@4450.29,-1363.09 4490.17,-1363.09 v1(4503.81,-1349.46) ; R2RB_IDL_17_12_TerB59.1@4401.98,-1261.11 4405,-1258.09 CRB_IDL_17_12_TerB59.1@4450.29,-1258.09 4503.17,-1258.09 v1(4503.81,-1257.46) ; R2RB_IDL_17_12_TerB58.1@4401.98,-1161.11 4447.27,-1161.11 CRB_IDL_17_12_TerB58.1@4450.29,-1158.09 4498.31,-1158.09 v1(4503.8,-1163.58) ; R2RB_IDL_17_12_TerB89.1@4403.38,-4317.34 4411.92,-4308.8 CRB_IDL_17_12_TerB89.1@4451.51,-4308.8 4489.69,-4308.8 v1(4505.03,-4293.46)
  Bot Signal w8: v1(-195.07,1509.11) -143.29,1509.11 CR_IDL_17_12_TerA68.1@-138.88,1504.7 -98.57,1504.7 R2R_IDL_17_12_TerA68.1@-90.8,1496.93 ; v1(-192.4,1214.36) -163.54,1214.36 CR_IDL_17_12_TerA71.1@-138.88,1189.7 -98.57,1189.7 R2R_IDL_17_12_TerA71.1@-90.8,1181.93 ; v1(-192.4,1306.36) -175.71,1306.36 -164.06,1294.7 CR_IDL_17_12_TerA70.1@-138.88,1294.7 -131.11,1286.93 R2R_IDL_17_12_TerA70.1@-90.8,1286.93 ; v1(-192.4,1628.36) -179.21,1628.36 -160.56,1609.7 CR_IDL_17_12_TerA67.1@-138.88,1609.7 -131.11,1601.93 R2R_IDL_17_12_TerA67.1@-90.8,1601.93 ; v1(-192.4,1720.36) -186.74,1714.7 CR_IDL_17_12_TerA66.1@-138.88,1714.7 -131.11,1706.93 R2R_IDL_17_12_TerA66.1@-90.8,1706.93 ; v1(-192.4,1950.36) -164.54,1950.36 CR_IDL_17_12_TerA64.1@-138.88,1924.7 -98.57,1924.7 R2R_IDL_17_12_TerA64.1@-90.8,1916.93 ; v1(-192.4,2364.36) -175.74,2347.7 CR_IDL_17_12_TerA60.1@-138.88,2347.7 -98.57,2347.7 R2R_IDL_17_12_TerA60.1@-90.8,2339.93 ; v1(-192.4,2456.36) -188.74,2452.7 CR_IDL_17_12_TerA59.1@-138.88,2452.7 -98.57,2452.7 R2R_IDL_17_12_TerA59.1@-90.8,2444.93 ; v1(-192.4,2686.36) -181.71,2686.36 -158.06,2662.7 CR_IDL_17_12_TerA57.1@-138.88,2662.7 -98.57,2662.7 R2R_IDL_17_12_TerA57.1@-90.8,2654.93 ; v1(-192.4,2778.36) -181.74,2767.7 CR_IDL_17_12_TerA56.1@-138.88,2767.7 -131.11,2759.93 R2R_IDL_17_12_TerA56.1@-90.8,2759.93 ; v1(-192.4,3100.36) -178.71,3100.36 -161.06,3082.7 CR_IDL_17_12_TerA53.1@-138.88,3082.7 -131.11,3074.93 R2R_IDL_17_12_TerA53.1@-90.8,3074.93 ; v1(-192.4,3192.36) -172.21,3192.36 -167.56,3187.7 CR_IDL_17_12_TerA52.1@-138.88,3187.7 -131.11,3179.93 R2R_IDL_17_12_TerA52.1@-90.8,3179.93 ; v1(-192.4,3422.36) -182.21,3422.36 -157.56,3397.7 CR_IDL_17_12_TerA50.1@-138.88,3397.7 -131.11,3389.93 R2R_IDL_17_12_TerA50.1@-90.8,3389.93 ; v1(-192.4,3514.36) -175.71,3514.36 -164.06,3502.7 CR_IDL_17_12_TerA49.1@-138.88,3502.7 -98.57,3502.7 R2R_IDL_17_12_TerA49.1@-90.8,3494.93 ; v1(-192.4,3836.36) -180.21,3836.36 -159.56,3815.7 CR_IDL_17_12_TerA46.1@-138.88,3815.7 -131.11,3807.93 R2R_IDL_17_12_TerA46.1@-90.8,3807.93 ; v1(-192.4,3928.36) -184.74,3920.7 CR_IDL_17_12_TerA45.1@-138.88,3920.7 -131.11,3912.93 R2R_IDL_17_12_TerA45.1@-90.8,3912.93 ; v1(-191.1,2251.19) -182.62,2242.7 CR_IDL_17_12_TerA61.1@-138.88,2242.7 -131.11,2234.93 R2R_IDL_17_12_TerA61.1@-90.8,2234.93 ; v1(-190.79,2874.17) -140.35,2874.17 CR_IDL_17_12_TerA55.1@-138.88,2872.7 -98.57,2872.7 R2R_IDL_17_12_TerA55.1@-90.8,2864.93 ; v1(-190.22,2984.75) -145.93,2984.75 CR_IDL_17_12_TerA54.1@-138.88,2977.7 -131.11,2969.93 R2R_IDL_17_12_TerA54.1@-90.8,2969.93 ; v1(-189.28,1820.25) -139.43,1820.25 CR_IDL_17_12_TerA65.1@-138.88,1819.7 -98.57,1819.7 R2R_IDL_17_12_TerA65.1@-90.8,1811.93 ; v1@-187.2,3607.7 CR_IDL_17_12_TerA48.1@-138.88,3607.7 -98.57,3607.7 R2R_IDL_17_12_TerA48.1@-90.8,3599.93 ; v1(-184.34,1407.76) -176.28,1399.7 CR_IDL_17_12_TerA69.1@-138.88,1399.7 -131.11,1391.93 R2R_IDL_17_12_TerA69.1@-90.8,1391.93 ; v1(-184.34,2565.76) -176.28,2557.7 CR_IDL_17_12_TerA58.1@-138.88,2557.7 -98.57,2557.7 R2R_IDL_17_12_TerA58.1@-90.8,2549.93 ; v1(-184.34,4033.76) -176.28,4025.7 CR_IDL_17_12_TerA44.1@-138.88,4025.7 -98.57,4025.7 R2R_IDL_17_12_TerA44.1@-90.8,4017.93 ; v1(-184.01,2127.28) -146.3,2127.28 CR_IDL_17_12_TerA62.1@-138.88,2134.7 -98.57,2134.7 R2R_IDL_17_12_TerA62.1@-90.8,2126.93 ; v1(-181.84,3718.86) -175.69,3712.7 CR_IDL_17_12_TerA47.1@-138.88,3712.7 -98.57,3712.7 R2R_IDL_17_12_TerA47.1@-90.8,3704.93 ; v1(-181.8,1076.15) -141.11,1076.15 -139.88,1074.93 CR_IDL_17_12_TerA72.1@-137.57,1077.24 -132.22,1071.89 R2R_IDL_17_12_TerA72.1@-89.67,1071.89 ; v1(-179.74,2029.7) CR_IDL_17_12_TerA63.1@-138.88,2029.7 -98.57,2029.7 R2R_IDL_17_12_TerA63.1@-90.8,2021.93 ; v1(-176.28,3292.7) CR_IDL_17_12_TerA51.1@-138.88,3292.7 -131.11,3284.93 R2R_IDL_17_12_TerA51.1@-90.8,3284.93 ; Jtop1.B23@128.79,3282.06 Jtop1.B23@132.51,3282.06 ; Jtop3.B20@1708.21,2979.68 Jtop3.B20@1748.13,2979.68 ; R2R_IDL_17_12_TerA14.1@2761.4,2187.45 2769.17,2195.22 CR_IDL_17_12_TerA14.1@2809.48,2195.22 2812.3,2198.04 v1(2860.75,2198.04) ; R2R_IDL_17_12_TerA13.1@2761.4,2292.45 2769.17,2300.22 CR_IDL_17_12_TerA13.1@2809.48,2300.22 2879.12,2300.22 v1(2888.98,2290.36) ; R2R_IDL_17_12_TerA12.1@2761.4,2397.45 2769.17,2405.22 CR_IDL_17_12_TerA12.1@2809.48,2405.22 2855.85,2405.22 v1(2858.61,2407.98) ; R2R_IDL_17_12_TerA11.1@2761.77,2580.66 2769.54,2588.43 CR_IDL_17_12_TerA11.1@2809.85,2588.43 2836.32,2588.43 v1(2862.33,2614.44) ; R2R_IDL_17_12_TerA10.1@2761.77,2775.66 2769.54,2783.43 CR_IDL_17_12_TerA10.1@2809.85,2783.43 2830.52,2783.43 2851.18,2804.09 v1(2863.37,2804.09) ; R2R_IDL_17_12_TerA9.1@2761.77,2975.66 2769.54,2983.43 CR_IDL_17_12_TerA9.1@2809.85,2983.43 2838.52,2983.43 2843.18,2988.09 v1(2863.37,2988.09) ; R2R_IDL_17_12_TerA8.1@2761.77,3240.66 2769.54,3248.43 CR_IDL_17_12_TerA8.1@2809.85,3248.43 2833.02,3248.43 2848.68,3264.09 v1(2863.37,3264.09) ; R2R_IDL_17_12_TerA7.1@2761.77,3345.66 2769.54,3353.43 CR_IDL_17_12_TerA7.1@2809.85,3353.43 2839.52,3353.43 2842.18,3356.09 v1(2863.37,3356.09) ; R2R_IDL_17_12_TerA6.1@2761.77,3450.66 2802.08,3450.66 CR_IDL_17_12_TerA6.1@2809.85,3458.43 2916.29,3458.43 v1(2936.37,3478.52) ; R2R_IDL_17_12_TerA5.1@2761.77,3555.66 2769.54,3563.43 CR_IDL_17_12_TerA5.1@2809.85,3563.43 2856.71,3563.43 v1(2863.37,3570.09) ; R2R_IDL_17_12_TerA4.1@2761.77,3660.66 2802.08,3660.66 CR_IDL_17_12_TerA4.1@2809.85,3668.43 2836.02,3668.43 2845.68,3678.09 v1(2847.37,3678.09) ; R2R_IDL_17_12_TerA3.1@2761.77,3765.66 2802.08,3765.66 CR_IDL_17_12_TerA3.1@2809.85,3773.43 2847.25,3773.43 v1(2855.31,3781.49) ; R2R_IDL_17_12_TerA2.1@2761.77,3870.66 2769.54,3878.43 CR_IDL_17_12_TerA2.1@2809.85,3878.43 2883.81,3878.43 v1(2885.8,3880.43) ; R2R_IDL_17_12_TerA1.1@2766.77,3981.9 2774.54,3989.67 CR_IDL_17_12_TerA1.1@2814.85,3989.67 2840.64,3989.67 2851.06,4000.09 v1(2868.37,4000.09) ; R2R_IDL_17_12_TerA22.1@2773.1,1158.8 2813.41,1158.8 CR_IDL_17_12_TerA22.1@2821.19,1166.58 2842.37,1187.76 v1(2874.71,1187.76) ; R2R_IDL_17_12_TerA21.1@2773.1,1263.8 2813.41,1263.8 CR_IDL_17_12_TerA21.1@2821.19,1271.58 2829.37,1279.76 v1(2874.71,1279.76) ; R2R_IDL_17_12_TerA20.1@2773.1,1368.8 2780.88,1376.58 CR_IDL_17_12_TerA20.1@2821.19,1376.58 2858.59,1376.58 2874.71,1392.7 v1(2874.71,1417.76) ; R2R_IDL_17_12_TerA19.1@2773.1,1473.8 2780.88,1481.58 CR_IDL_17_12_TerA19.1@2821.19,1481.58 2862.52,1481.58 v1(2874.71,1493.76) ; R2R_IDL_17_12_TerA18.1@2773.1,1578.8 2813.41,1578.8 CR_IDL_17_12_TerA18.1@2821.19,1586.58 2859.52,1586.58 v1(2874.71,1601.76) ; R2R_IDL_17_12_TerA17.1@2773.1,1683.8 2813.41,1683.8 CR_IDL_17_12_TerA17.1@2821.19,1691.58 2823.37,1693.76 v1(2874.71,1693.76) ; R2R_IDL_17_12_TerA16.1@2773.1,1786.8 2780.88,1794.58 CR_IDL_17_12_TerA16.1@2821.19,1794.58 2858.59,1794.58 2874.71,1810.7 v1(2874.71,1831.76) ; v1(2774.09,1006.49) 2774.09,1052.82 R2R_IDL_17_12_TerA23.1@2773.1,1053.8 2813.41,1053.8 CR_IDL_17_12_TerA23.1@2821.19,1061.58 ; R2R_IDL_17_12_TerA15.1@2775.18,1975.28 CR_IDL_17_12_TerA15.1@2815.49,1975.28 2846.08,1975.28 2846.89,1976.09 v1(2869.01,1976.09)
  other v1: 3959.07,-2889.23 -187.2,3608.23
IACKIN_5: Jtop1.A21 Jtop2.A21 Jtop3.A21 Jtop4.A21 | length 2525.3
  Top Signal w8: Jtop1.A21@228.79,3082.06 241.64,3082.06 287.83,3035.87 835.78,3035.87 841.3,3041.38 895.08,3041.38 900.59,3035.87 935.78,3035.87 941.3,3041.38 987.61,3041.38 1028.72,3082.48 1077.45,3033.76 1646.87,3033.76 1652.75,3039.63 1705.81,3039.63 1711.68,3033.76 1746.87,3033.76 1752.75,3039.63 1786.29,3039.63 Jtop3.A21@1823.97,3077.31 ; Jtop3.A21@1805.98,3077.31 Jtop3.A21@1823.97,3077.31 ; Jtop3.A21@1828.72,3082.06 Jtop3.A21@1823.97,3077.31 ; Jtop4.A21@2605.98,3071.78 2563.73,3029.52 1894.05,3029.52 1846.26,3077.31 Jtop3.A21@1823.97,3077.31
IACKOUT_5: Jtop1.A22 Jtop2.A22 Jtop3.A22 Jtop4.A22 | length 2525.9
  Top Signal w8: Jtop1.A22@228.79,3182.06 270.85,3140 796.46,3140 800.59,3135.87 835.78,3135.87 839.92,3140 896.46,3140 900.59,3135.87 935.78,3135.87 939.92,3140 986.24,3140 Jtop2.A22@1018.19,3171.95 ; Jtop2.A22@1018.19,3178.35 Jtop2.A22@1018.19,3171.95 ; Jtop4.A22@2622.31,3177.05 2569.81,3124.54 1880.97,3124.54 Jtop3.A22@1829.28,3176.24 1790.6,3137.55 1750.67,3137.55 1746.87,3133.76 1711.68,3133.76 1707.89,3137.55 1650.67,3137.55 1646.87,3133.76 1077.45,3133.76 1028.72,3182.48 Jtop2.A22@1018.19,3171.95
JB1: Jbot1.A32 Jbot2.A32 Jbot3.A32 Jbot4.A32 R1RB_IDL_17_12_TerB1.1 R2RB_IDL_17_12_TerB1.2 | length 3349.7
  Top Signal w8: Jbot1.A32@228.26,-1073.77 268.54,-1073.77 310.6,-1115.83 857.77,-1115.83 ; 857.79,-1115.8 910.57,-1115.8 ; 910.59,-1115.83 945.79,-1115.83 988.27,-1073.35 Jbot2.A32@1028.19,-1073.35 1067.63,-1073.35 1110.53,-1116.25 1785.71,-1116.25 Jbot3.A32@1828.19,-1073.77 1837.73,-1073.77 1880.21,-1116.25 2591.25,-1116.25 2630.96,-1076.54 2645.8,-1061.69 R2RB_IDL_17_12_TerB1.2@3414.3,-1061.69 3414.3,-1036 3413.79,-1035.49 R1RB_IDL_17_12_TerB1.1@3413.79,-1008.84
JB2: Jbot1.A31 Jbot2.A31 Jbot3.A31 Jbot4.A31 R1RB_IDL_17_12_TerB2.1 R2RB_IDL_17_12_TerB2.2 | length 3352.3
  Top Signal w8: Jbot1.A31@228.26,-1173.77 268.54,-1173.77 310.6,-1215.83 945.79,-1215.83 988.27,-1173.35 Jbot2.A31@1028.19,-1173.35 1067.63,-1173.35 1110.53,-1216.25 1785.71,-1216.25 Jbot3.A31@1828.19,-1173.77 ; Jbot3.A31@1830.51,-1173.38 1847.8,-1173.38 1899.29,-1224.87 2401.97,-1224.87 2410.59,-1216.25 2593.18,-1216.25 2631.92,-1177.5 2640.26,-1169.17 R2RB_IDL_17_12_TerB2.2@3414.99,-1169.17 3414.99,-1143 3414.48,-1142.49 R1RB_IDL_17_12_TerB2.1@3414.48,-1116.31
JB3: Jbot1.A30 Jbot2.A30 Jbot3.A30 Jbot4.A30 R1RB_IDL_17_12_TerB3.1 R2RB_IDL_17_12_TerB3.2 | length 3345
  Top Signal w8: Jbot1.A30@228.26,-1273.77 268.54,-1273.77 310.6,-1315.83 858.56,-1315.83 858.98,-1315.4 910.17,-1315.4 910.59,-1315.83 945.79,-1315.83 988.27,-1273.35 Jbot2.A30@1028.19,-1273.35 1067.63,-1273.35 1110.53,-1316.25 1785.71,-1316.25 Jbot3.A30@1825.49,-1276.46 ; Jbot3.A30@1815.45,-1276.46 Jbot3.A30@1825.49,-1276.46 ; Jbot3.A30@1828.19,-1273.77 Jbot3.A30@1825.49,-1276.46 ; Jbot4.A30@2615.45,-1282 2578.51,-1318.94 2553.24,-1318.94 2551.58,-1317.29 2504.8,-1317.29 2503.14,-1318.94 1898.21,-1318.94 1855.73,-1276.46 1828.19,-1276.46 Jbot3.A30@1825.49,-1276.46 ; Jbot4.A30@2628.19,-1273.77 2628.59,-1274.17 R2RB_IDL_17_12_TerB3.2@3414.99,-1274.17 3414.99,-1248 3414.48,-1247.49 R1RB_IDL_17_12_TerB3.1@3414.48,-1221.31
JB4: Jbot1.A29 Jbot2.A29 Jbot3.A29 Jbot4.A29 R1RB_IDL_17_12_TerB4.1 R2RB_IDL_17_12_TerB4.2 | length 3354.2
  Top Signal w8: Jbot1.A29@228.26,-1373.77 268.54,-1373.77 310.6,-1415.83 985.71,-1415.83 Jbot2.A29@1028.19,-1373.35 1067.63,-1373.35 1110.53,-1416.25 1785.71,-1416.25 Jbot3.A29@1828.19,-1373.77 1871.82,-1417.4 2504.68,-1417.4 2504.8,-1417.29 2551.58,-1417.29 2551.7,-1417.4 2601.67,-1417.4 2636.75,-1382.32 Jbot4.A29@2638.61,-1380.46 ; Jbot4.A29@2628.19,-1373.77 2628.59,-1374.17 R2RB_IDL_17_12_TerB4.2@3414.99,-1374.17 3414.99,-1348 3414.48,-1347.49 R1RB_IDL_17_12_TerB4.1@3414.48,-1321.31
JB5: Jbot1.A28 Jbot2.A28 Jbot3.A28 Jbot4.A28 R1RB_IDL_17_12_TerB5.1 R2RB_IDL_17_12_TerB5.2 | length 3346.6
  Top Signal w8: Jbot1.A28@228.26,-1473.77 268.54,-1473.77 310.6,-1515.83 985.71,-1515.83 Jbot2.A28@1028.19,-1473.35 1067.63,-1473.35 1110.53,-1516.25 1785.71,-1516.25 Jbot3.A28@1828.19,-1473.77 ; Jbot3.A28@1806.18,-1473.37 1828.19,-1473.37 1846.46,-1473.37 1889.34,-1516.25 2568.85,-1516.25 Jbot4.A28@2606.18,-1478.91 ; Jbot4.A28@2628.19,-1473.77 2632.22,-1477.8 3411.36,-1477.8 R2RB_IDL_17_12_TerB5.2@3414.99,-1474.17 3414.99,-1448 3414.48,-1447.49 R1RB_IDL_17_12_TerB5.1@3414.48,-1421.31
JB6: Jbot1.A27 Jbot2.A27 Jbot3.A27 Jbot4.A27 R1RB_IDL_17_12_TerB6.1 R2RB_IDL_17_12_TerB6.2 | length 3343.2
  Top Signal w8: Jbot1.A27@228.26,-1573.77 268.54,-1573.77 310.6,-1615.83 985.71,-1615.83 Jbot2.A27@1028.19,-1573.35 1071.09,-1616.25 1785.71,-1616.25 Jbot3.A27@1826.06,-1575.9 ; Jbot3.A27@1815.13,-1575.9 Jbot3.A27@1826.06,-1575.9 ; Jbot3.A27@1828.19,-1573.77 Jbot3.A27@1826.06,-1575.9 ; Jbot4.A27@2615.13,-1581.44 2578.19,-1618.38 1897.89,-1618.38 1855.4,-1575.9 1828.19,-1575.9 Jbot3.A27@1826.06,-1575.9 ; Jbot4.A27@2628.19,-1573.77 2628.59,-1574.17 R2RB_IDL_17_12_TerB6.2@3414.99,-1574.17 3414.99,-1548 3414.48,-1547.49 R1RB_IDL_17_12_TerB6.1@3414.48,-1521.31
JB7: Jbot1.A26 Jbot2.A26 Jbot3.A26 Jbot4.A26 R1RB_IDL_17_12_TerB7.1 R2RB_IDL_17_12_TerB7.2 | length 3345.4
  Top Signal w8: Jbot1.A26@228.26,-1673.77 268.54,-1673.77 310.6,-1715.83 985.71,-1715.83 Jbot2.A26@1028.19,-1673.35 1067.63,-1673.35 1110.53,-1716.25 1785.71,-1716.25 Jbot3.A26@1828.19,-1673.77 ; Jbot3.A26@1819.36,-1672.7 1828.19,-1672.7 1859.64,-1672.7 1903.18,-1716.25 2581.36,-1716.25 Jbot4.A26@2619.36,-1678.24 ; Jbot4.A26@2628.19,-1673.77 2631.59,-1677.17 R2RB_IDL_17_12_TerB7.2@3414.99,-1677.17 3414.99,-1651 3414.48,-1650.49 R1RB_IDL_17_12_TerB7.1@3414.48,-1624.31
JB8: Jbot1.A25 Jbot2.A25 Jbot3.A25 Jbot4.A25 R1RB_IDL_17_12_TerB8.1 R2RB_IDL_17_12_TerB8.2 | length 3345.1
  Top Signal w8: Jbot1.A25@228.26,-1773.77 268.54,-1773.77 310.6,-1815.83 985.71,-1815.83 Jbot2.A25@1028.19,-1773.35 1071.09,-1816.25 1785.71,-1816.25 Jbot3.A25@1826.4,-1775.56 ; Jbot3.A25@1816.34,-1775.56 Jbot3.A25@1826.4,-1775.56 ; Jbot3.A25@1828.19,-1773.77 Jbot3.A25@1826.4,-1775.56 ; Jbot4.A25@2616.34,-1781.1 2579.4,-1818.04 2552.34,-1818.04 2551.58,-1817.29 2504.8,-1817.29 2504.04,-1818.04 1899.1,-1818.04 1856.61,-1775.56 1828.19,-1775.56 Jbot3.A25@1826.4,-1775.56 ; Jbot4.A25@2628.19,-1773.77 2631.59,-1777.17 R2RB_IDL_17_12_TerB8.2@3414.99,-1777.17 3414.99,-1724.82 R1RB_IDL_17_12_TerB8.1@3414.48,-1724.31
JB9: Jbot1.A24 Jbot2.A24 Jbot3.A24 Jbot4.A24 R1RB_IDL_17_12_TerB9.1 R2RB_IDL_17_12_TerB9.2 | length 3344.6
  Top Signal w8: Jbot1.A24@228.26,-1873.77 268.54,-1873.77 310.6,-1915.83 985.71,-1915.83 Jbot2.A24@1028.19,-1873.35 1044.05,-1873.35 1086.95,-1916.25 1785.71,-1916.25 Jbot3.A24@1827.17,-1874.79 ; Jbot3.A24@1818.15,-1874.79 Jbot3.A24@1827.17,-1874.79 ; Jbot3.A24@1828.19,-1873.77 Jbot3.A24@1827.17,-1874.79 ; Jbot4.A24@2618.15,-1880.33 2581.21,-1917.27 1900.91,-1917.27 1858.43,-1874.79 1828.19,-1874.79 Jbot3.A24@1827.17,-1874.79 ; Jbot4.A24@2628.19,-1873.77 2631.73,-1877.31 3022.26,-1877.31 3022.4,-1877.17 R2RB_IDL_17_12_TerB9.2@3414.99,-1877.17 3414.99,-1851 3414.48,-1850.49 R1RB_IDL_17_12_TerB9.1@3414.48,-1824.31
JB10: Jbot1.A23 Jbot2.A23 Jbot3.A23 Jbot4.A23 R1RB_IDL_17_12_TerB10.1 R2RB_IDL_17_12_TerB10.2 | length 3345
  Top Signal w8: Jbot1.A23@228.26,-1973.77 268.54,-1973.77 310.6,-2015.83 985.71,-2015.83 Jbot2.A23@1028.19,-1973.35 1071.66,-2016.81 1785.14,-2016.81 Jbot3.A23@1823.71,-1978.25 ; Jbot3.A23@1816.94,-1978.25 Jbot3.A23@1823.71,-1978.25 ; Jbot3.A23@1828.19,-1973.77 Jbot3.A23@1823.71,-1978.25 ; Jbot4.A23@2616.94,-1983.79 2580,-2020.73 1899.7,-2020.73 1857.22,-1978.25 1828.19,-1978.25 Jbot3.A23@1823.71,-1978.25 ; Jbot4.A23@2628.19,-1973.77 2631.63,-1977.21 3022.36,-1977.21 3022.4,-1977.17 R2RB_IDL_17_12_TerB10.2@3414.99,-1977.17 3414.99,-1951 3414.48,-1950.49 R1RB_IDL_17_12_TerB10.1@3414.48,-1924.31
JB11: Jbot1.A22 Jbot2.A22 Jbot3.A22 Jbot4.A22 R1RB_IDL_17_12_TerB11.1 R2RB_IDL_17_12_TerB11.2 | length 3348.6
  Top Signal w8: Jbot1.A22@228.26,-2073.77 268.54,-2073.77 310.6,-2115.83 985.71,-2115.83 Jbot2.A22@1028.19,-2073.35 1072.03,-2117.18 1784.77,-2117.18 Jbot3.A22@1828.19,-2073.77 ; Jbot3.A22@1821.78,-2073.24 1828.19,-2073.24 1828.45,-2073.5 1872.23,-2117.28 2583.28,-2117.28 Jbot4.A22@2621.78,-2078.78 ; Jbot4.A22@2628.19,-2073.77 2636.59,-2082.17 R2RB_IDL_17_12_TerB11.2@3414.99,-2082.17 3414.99,-2056 3414.48,-2055.49 R1RB_IDL_17_12_TerB11.1@3414.48,-2029.31
JB12: Jbot1.A21 Jbot2.A21 Jbot3.A21 Jbot4.A21 R1RB_IDL_17_12_TerB12.1 R2RB_IDL_17_12_TerB12.2 | length 3343.2
  Top Signal w8: Jbot1.A21@228.26,-2173.77 268.54,-2173.77 310.6,-2215.83 985.71,-2215.83 Jbot2.A21@1028.19,-2173.35 1071.09,-2216.25 1785.71,-2216.25 Jbot3.A21@1823.44,-2178.51 ; Jbot3.A21@1805.45,-2178.51 Jbot3.A21@1823.44,-2178.51 ; Jbot3.A21@1828.19,-2173.77 Jbot3.A21@1823.44,-2178.51 ; Jbot4.A21@2605.45,-2184.05 2572.51,-2216.99 1884.2,-2216.99 1845.72,-2178.51 1828.19,-2178.51 Jbot3.A21@1823.44,-2178.51 ; Jbot4.A21@2628.19,-2173.77 2636.59,-2182.17 R2RB_IDL_17_12_TerB12.2@3414.99,-2182.17 3414.99,-2156 3414.48,-2155.49 R1RB_IDL_17_12_TerB12.1@3414.48,-2129.31
JB13: Jbot1.A20 Jbot2.A20 Jbot3.A20 Jbot4.A20 R1RB_IDL_17_12_TerB13.1 R2RB_IDL_17_12_TerB13.2 | length 3344.4
  Top Signal w8: Jbot1.A20@228.26,-2273.77 268.54,-2273.77 310.6,-2315.83 985.71,-2315.83 Jbot2.A20@1028.19,-2273.35 1067.63,-2273.35 1110.53,-2316.25 1785.71,-2316.25 Jbot3.A20@1825.43,-2276.53 ; Jbot3.A20@1807.26,-2276.53 Jbot3.A20@1825.43,-2276.53 ; Jbot3.A20@1828.19,-2273.77 Jbot3.A20@1825.43,-2276.53 ; Jbot4.A20@2607.26,-2282.07 2572.98,-2316.35 1887.36,-2316.35 1847.54,-2276.53 1828.19,-2276.53 Jbot3.A20@1825.43,-2276.53 ; Jbot4.A20@2628.19,-2273.77 2636.59,-2282.17 R2RB_IDL_17_12_TerB13.2@3414.99,-2282.17 3414.99,-2256 3414.48,-2255.49 R1RB_IDL_17_12_TerB13.1@3414.48,-2229.31
JB14: Jbot1.A19 Jbot2.A19 Jbot3.A19 Jbot4.A19 R1RB_IDL_17_12_TerB14.1 R2RB_IDL_17_12_TerB14.2 | length 3347.3
  Top Signal w8: Jbot1.A19@228.26,-2373.77 268.54,-2373.77 310.6,-2415.83 985.71,-2415.83 Jbot2.A19@1028.19,-2373.35 1071.09,-2416.25 1785.71,-2416.25 Jbot3.A19@1826.2,-2375.76 ; Jbot3.A19@1816.94,-2375.76 Jbot3.A19@1826.2,-2375.76 ; Jbot3.A19@1828.19,-2373.77 Jbot3.A19@1826.2,-2375.76 ; Jbot4.A19@2616.94,-2381.3 2580,-2418.24 2552.54,-2418.24 2551.58,-2417.29 2504.8,-2417.29 2503.84,-2418.24 1899.7,-2418.24 1857.22,-2375.76 1828.19,-2375.76 Jbot3.A19@1826.2,-2375.76 ; Jbot4.A19@2628.19,-2373.77 2636.59,-2382.17 R2RB_IDL_17_12_TerB14.2@3414.99,-2382.17 3414.99,-2356 3414.48,-2355.49 R1RB_IDL_17_12_TerB14.1@3414.48,-2329.31
JB15: Jbot1.A18 Jbot2.A18 Jbot3.A18 Jbot4.A18 R1RB_IDL_17_12_TerB15.1 R2RB_IDL_17_12_TerB15.2 | length 3349.2
  Top Signal w8: Jbot1.A18@228.26,-2473.77 268.54,-2473.77 310.6,-2515.83 985.71,-2515.83 Jbot2.A18@1028.19,-2473.35 1071.09,-2516.25 1785.71,-2516.25 Jbot3.A18@1826.37,-2475.59 ; Jbot3.A18@1804.84,-2475.59 Jbot3.A18@1826.37,-2475.59 ; Jbot3.A18@1828.19,-2473.77 Jbot3.A18@1826.37,-2475.59 ; Jbot4.A18@2604.84,-2481.13 2567.9,-2518.07 1887.6,-2518.07 1845.12,-2475.59 1828.19,-2475.59 Jbot3.A18@1826.37,-2475.59 ; Jbot4.A18@2628.19,-2473.77 2639.79,-2485.36 3411.8,-2485.36 R2RB_IDL_17_12_TerB15.2@3414.99,-2482.17 3414.99,-2456 3414.48,-2455.49 R1RB_IDL_17_12_TerB15.1@3414.48,-2429.31
JB16: Jbot1.A17 Jbot2.A17 Jbot3.A17 Jbot4.A17 R1RB_IDL_17_12_TerB16.1 R2RB_IDL_17_12_TerB16.2 | length 3353
  Top Signal w8: Jbot1.A17@228.26,-2573.77 268.54,-2573.77 310.6,-2615.83 985.71,-2615.83 Jbot2.A17@1028.19,-2573.35 1071.54,-2616.7 1785.26,-2616.7 Jbot3.A17@1828.19,-2573.77 ; Jbot3.A17@1816.94,-2569.37 1828.19,-2569.37 1857.22,-2569.37 1904.54,-2616.69 2575.16,-2616.69 Jbot4.A17@2616.94,-2574.91 ; Jbot4.A17@2628.19,-2573.77 2641.59,-2587.17 R2RB_IDL_17_12_TerB16.2@3414.99,-2587.17 3414.99,-2561 3414.48,-2560.49 R1RB_IDL_17_12_TerB16.1@3414.48,-2534.31
JB17: Jbot1.A16 Jbot2.A16 Jbot3.A16 Jbot4.A16 R1RB_IDL_17_12_TerB17.1 R2RB_IDL_17_12_TerB17.2 | length 3363.7
  Top Signal w8: Jbot1.A16@228.26,-2673.77 268.54,-2673.77 310.6,-2715.83 985.71,-2715.83 Jbot2.A16@1028.19,-2673.35 1068.47,-2673.35 1111.37,-2716.25 1645.78,-2716.25 1647.91,-2714.12 1708.46,-2714.12 1710.59,-2716.25 1745.78,-2716.25 1788.27,-2673.77 Jbot3.A16@1828.19,-2673.77 ; Jbot3.A16@1828.58,-2663.89 1868.86,-2663.89 1916.78,-2711.82 2406.16,-2711.82 2410.59,-2716.25 2445.78,-2716.25 2450.22,-2711.82 2506.16,-2711.82 2510.59,-2716.25 2581.76,-2716.25 2626.22,-2671.79 2628.58,-2669.43 2630.55,-2671.4 2646.32,-2687.17 R2RB_IDL_17_12_TerB17.2@3414.99,-2687.17 3414.99,-2661 3414.48,-2660.49 R1RB_IDL_17_12_TerB17.1@3414.48,-2634.31
JB18: Jbot1.A15 Jbot2.A15 Jbot3.A15 Jbot4.A15 R1RB_IDL_17_12_TerB18.1 R2RB_IDL_17_12_TerB18.2 | length 3356.1
  Top Signal w8: Jbot1.A15@228.26,-2773.77 268.54,-2773.77 310.6,-2815.83 985.71,-2815.83 Jbot2.A15@1028.19,-2773.35 1068.47,-2773.35 1111.37,-2816.25 1746.23,-2816.25 1746.67,-2815.8 1791.98,-2815.8 1828.19,-2779.6 Jbot3.A15@1828.19,-2773.77 ; Jbot3.A15@1819.17,-2770 1828.19,-2770 1859.44,-2770 1905.69,-2816.25 2445.78,-2816.25 2446.95,-2815.08 2509.43,-2815.08 2510.59,-2816.25 2578.46,-2816.25 Jbot4.A15@2619.17,-2775.54 ; Jbot4.A15@2628.19,-2773.77 2641.59,-2787.17 R2RB_IDL_17_12_TerB18.2@3414.99,-2787.17 3414.99,-2761 3414.48,-2760.49 R1RB_IDL_17_12_TerB18.1@3414.48,-2734.31
JB19: Jbot1.A14 Jbot2.A14 Jbot3.A14 Jbot4.A14 R1RB_IDL_17_12_TerB19.1 R2RB_IDL_17_12_TerB19.2 | length 3363.6
  Top Signal w8: Jbot1.A14@228.26,-2873.77 268.54,-2873.77 310.6,-2915.83 985.71,-2915.83 Jbot2.A14@1028.19,-2873.35 1068.47,-2873.35 1111.37,-2916.25 1785.71,-2916.25 Jbot3.A14@1828.19,-2873.77 ; Jbot3.A14@1817.75,-2870.78 1828.19,-2870.78 1858.03,-2870.78 1903.5,-2916.25 2390.47,-2916.25 2405.51,-2931.29 2450.87,-2931.29 2464.87,-2917.29 2576.78,-2917.29 Jbot4.A14@2617.75,-2876.32 ; Jbot4.A14@2628.19,-2873.77 2641.59,-2887.17 R2RB_IDL_17_12_TerB19.2@3414.99,-2887.17 3414.99,-2861 3414.48,-2860.49 R1RB_IDL_17_12_TerB19.1@3414.48,-2834.31
JB20: Jbot1.A13 Jbot2.A13 Jbot3.A13 Jbot4.A13 R1RB_IDL_17_12_TerB20.1 R2RB_IDL_17_12_TerB20.2 | length 3345.9
  Top Signal w8: Jbot1.A13@228.26,-2973.77 268.54,-2973.77 310.6,-3015.83 985.71,-3015.83 Jbot2.A13@1028.19,-2973.35 1037.82,-2973.35 1080.72,-3016.25 1645.79,-3016.25 1646.06,-3015.97 1710.32,-3015.97 1710.59,-3016.25 1745.79,-3016.25 1747.07,-3014.96 1770.73,-3014.96 1811.93,-2973.77 Jbot3.A13@1828.19,-2973.77 1894.46,-2973.77 1938.56,-3017.87 2585.53,-3017.87 Jbot4.A13@2622.47,-2980.93 ; Jbot4.A13@2628.19,-2973.77 2646.59,-2992.17 R2RB_IDL_17_12_TerB20.2@3414.99,-2992.17 3414.99,-2966 3414.48,-2965.49 R1RB_IDL_17_12_TerB20.1@3414.48,-2939.31
JB21: Jbot1.A12 Jbot2.A12 Jbot3.A12 Jbot4.A12 R1RB_IDL_17_12_TerB21.1 R2RB_IDL_17_12_TerB21.2 | length 3352.9
  Top Signal w8: Jbot1.A12@228.26,-3073.77 268.54,-3073.77 310.6,-3115.83 985.71,-3115.83 Jbot2.A12@1028.19,-3073.35 1071.09,-3116.25 1645.79,-3116.25 1646.42,-3115.61 1709.96,-3115.61 1710.59,-3116.25 1745.79,-3116.25 1746.42,-3115.61 1786.34,-3115.61 Jbot3.A12@1828.19,-3073.77 1869.45,-3115.03 2409.38,-3115.03 2410.59,-3116.25 2445.78,-3116.25 2447,-3115.03 2509.38,-3115.03 2510.59,-3116.25 2583.9,-3116.25 Jbot4.A12@2622.47,-3077.67 ; Jbot3.A12@1822.47,-3072.13 Jbot3.A12@1828.19,-3072.13 ; Jbot4.A12@2628.19,-3073.77 2646.59,-3092.17 R2RB_IDL_17_12_TerB21.2@3414.99,-3092.17 3414.99,-3066 3414.48,-3065.49 R1RB_IDL_17_12_TerB21.1@3414.48,-3039.31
